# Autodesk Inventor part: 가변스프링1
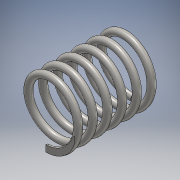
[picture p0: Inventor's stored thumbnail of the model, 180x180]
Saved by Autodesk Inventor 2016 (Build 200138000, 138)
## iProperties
Created: 2021-02
Part Number: 가변스프링1
Material: 강철, 탄소
Document SubType Name: Modeling
Designer: Windows7
Density: 7.85 g/cm^3
Appearance: 반연마
Mass: 7.77533 g
Surface Area: 20.0935 cm^2
Volume: 0.990488 cm^3
Author: Windows7
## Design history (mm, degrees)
sketch "스케치1"
  geometry: L1 (0, 0)-(26.33, 0); L2 (26.33, 0)-(26.33, -8.5); L3 (26.33, -8.5)-(0, -8.5); L4 (0, -8.5)-(0, 0); C1 r 1 at (26.33, -8.5)
  constraints: 8 end point, 2 parallel, 1 centre point, 1 coincident, 1 horizontal, 1 perpendicular
  dimensions: "d0" = 26.33013 distance between parallel lines of L4 L2 (derived); "d1" = 17 diameter of L3 L1; "d2" = 2 diameter of C1
feature "코일1" sketch "스케치1" pitch "d3" = 10; turns "d5" = 6; dims "d4" = 26.33013 (= d0), "d6" = 0, angle "d7" = 90 deg, angle "d8" = 90 deg, "d9" = 0, "d10" = 0
sketch "스케치2"
  geometry: L1 (0, -7.5)-(0, -9.5) reference; 1 further point
  constraints: 1 vertical alignment
extrude "돌출1" cut sketch "스케치2" distance "d11" = 10; taper "d12" = 0 deg
node "작업 평면1"
sketch "스케치3"
  geometry: L1 (7.5, 0)-(9.5, 0) reference; 2 further points
  constraints: 2 other
extrude "돌출2" cut sketch "스케치3" distance "d14" = 10; taper "d15" = 0 deg
node "솔리드1"
node "절단 모서리 투영1"
node "절단 모서리 투영2"
other parameters: "d13" = 90 deg
